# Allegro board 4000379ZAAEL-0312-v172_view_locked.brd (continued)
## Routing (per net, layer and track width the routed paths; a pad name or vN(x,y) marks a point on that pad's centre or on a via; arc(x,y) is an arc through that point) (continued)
DDR_BL3_DQ26: length 67.9
  TOP w0.102: U13.A3 95.77,15.19 95.77,12.59 95.24,12.06 89.84,12.06 82.37,19.53 82.37,37.54 82.45,37.62 85.34,37.62 85.42,37.69 85.42,37.97 85.34,38.05 83.35,38.05 83.26,38.14 83.26,38.38 83.46,38.58 85.27,38.58 85.34,38.66 85.34,39.04 85.27,39.12 84.43,39.12 84.35,39.19 84.35,39.45 84.54,39.64 85.42,39.64 85.5,39.71 85.5,40.62 85.59,40.7 86.4,40.7 86.5,40.8 86.5,41.62 94.09,49.21 96,49.21 96.47,48.74 97.06,48.74 97.19,48.87 98.68,48.87 98.79,48.76 99.04,48.76 99.37,49.08 U1.N26
DDR_BL3_DQ27: length 67.7
  TOP w0.102: U1.K27 99.24,47.68 98.81,47.68 98.68,47.55 97.87,47.55 97.19,46.86 94.93,46.86 88.77,40.71 88.77,32.64 88.7,32.56 87.76,32.56 87.68,32.64 87.68,32.97 87.76,33.05 88.21,33.05 88.29,33.12 88.29,33.38 88.21,33.45 87.86,33.45 87.78,33.53 87.78,33.78 87.86,33.86 88.21,33.86 88.29,33.93 88.29,34.32 88.21,34.39 87.35,34.39 87.27,34.32 87.27,32.64 87.2,32.56 86.94,32.56 86.87,32.64 86.87,34.32 86.79,34.39 86.54,34.39 86.46,34.32 86.46,32.64 86.39,32.56 86.13,32.56 86.06,32.64 86.06,34.32 85.98,34.39 85.72,34.39 85.65,34.32 85.65,32.64 85.57,32.56 85.32,32.56 85.24,32.64 85.24,34.32 85.17,34.39 84.89,34.39 84.81,34.32 84.81,23.97 85.58,23.2 85.58,22.8 85.7,22.68 86.09,22.68 86.23,22.54 86.23,22.28 86.33,22.17 86.6,22.17 87.05,21.73 87.05,21.51 87.14,21.41 87.41,21.41 87.53,21.3 87.53,20.91 87.66,20.78 87.91,20.78 88.04,20.65 88.04,16.97 90.49,14.51 92.97,14.51 93.12,14.66 93.12,15.47 92.99,15.6 92.16,15.6 91.77,15.99 U13.B8
DDR_BL3_DQ28: length 67.9
  TOP w0.102: U1.P27 98.91,49.51 98.68,49.28 97.05,49.28 96.93,49.15 96.7,49.15 96.14,49.71 93.69,49.71 81.76,37.78 81.76,19.24 89.55,11.46 95.49,11.46 98.57,14.53 98.57,16.42 97.79,17.2 96.42,17.2 96.01,16.79 95.77,16.79 U13.C3
DDR_BL3_DQ29: length 68
  TOP w0.102: U1.J26 99.37,47.36 99.04,47.03 98.79,47.03 98.67,47.14 98.04,47.14 97.3,46.41 95.33,46.41 90.98,42.05 90.98,35.15 90.91,35.08 90.53,35.08 90.45,35 90.45,34.77 90.53,34.7 90.91,34.7 90.98,34.62 90.98,34.32 90.91,34.24 89.53,34.24 89.46,34.16 89.46,33.78 89.53,33.71 90.91,33.71 90.98,33.63 90.98,33.32 90.91,33.25 90.45,33.25 90.37,33.17 90.37,32.61 90.45,32.54 90.91,32.54 90.98,32.46 90.98,31.95 90.91,31.88 89.99,31.88 89.92,31.95 89.92,33.17 89.84,33.25 89.53,33.25 89.46,33.17 89.46,31.95 89.38,31.88 87.15,31.88 87.07,31.8 87.07,28.75 87,28.68 86.74,28.68 86.66,28.75 86.66,31.8 86.59,31.88 86.33,31.88 86.26,31.8 86.26,28.68 86.18,28.6 85.93,28.6 85.85,28.68 85.85,31.8 85.78,31.88 85.5,31.88 85.42,31.8 85.42,24.22 88.85,20.79 88.85,17.03 89.49,16.39 92.05,16.39 92.18,16.52 92.18,17.46 92.3,17.59 92.56,17.59 U13.D7
DDR_BL3_DQ30: length 66.7
  TOP w0.102: U13.A2 96.57,15.19 96.57,15.18 96.57,15.12 96.46,15.01 96.23,15.01 96.14,15.09 96.14,15.36 95.94,15.57 95.4,15.57 95.33,15.49 95.33,12.75 94.95,12.37 89.98,12.37 82.68,19.67 82.68,37.13 82.75,37.21 86.79,37.21 86.87,37.29 86.87,37.64 86.79,37.72 85.86,37.72 85.79,37.8 85.79,38.15 85.86,38.23 86.79,38.23 86.87,38.3 86.87,38.66 86.79,38.73 85.88,38.73 85.8,38.81 85.8,39.17 85.88,39.24 86.79,39.24 86.87,39.32 86.87,39.67 86.79,39.75 86.11,39.75 86.03,39.83 86.03,40.18 86.11,40.26 86.79,40.26 86.87,40.34 86.87,41.54 94.29,48.96 95.93,48.96 96.35,48.54 97.13,48.54 97.25,48.66 98.51,48.66 U1.M29
DDR_BL3_DQ31: length 67.2
  TOP w0.102: U13.C8 91.77,16.79 91.77,17.1 91.67,17.2 90.73,17.2 90.53,17.4 90.15,17.4 90.07,17.48 90.07,17.91 89.99,17.98 89.71,17.98 89.64,17.91 89.64,17.63 89.54,17.53 89.25,17.53 89.15,17.62 89.15,20.92 85.72,24.34 85.72,28.14 85.8,28.22 87.33,28.22 87.4,28.3 87.4,31.5 87.48,31.57 91.26,31.57 91.36,31.67 91.36,32.36 91.44,32.44 92.25,32.44 92.33,32.51 92.33,32.77 92.25,32.84 91.44,32.84 91.36,32.92 91.36,33.17 91.44,33.25 92.35,33.25 92.43,33.32 92.43,33.55 92.35,33.63 91.44,33.63 91.36,33.71 91.36,33.99 91.44,34.06 92.35,34.06 92.43,34.14 92.43,34.39 92.35,34.47 91.44,34.47 91.36,34.54 91.36,34.8 91.44,34.87 92.35,34.87 92.43,34.95 92.43,35.2 92.35,35.28 91.44,35.28 91.36,35.36 91.36,35.61 91.44,35.69 92.35,35.69 92.43,35.76 92.43,36.02 92.35,36.09 91.44,36.09 91.36,36.17 91.36,36.42 91.44,36.5 92.35,36.5 92.43,36.58 92.43,36.83 92.35,36.91 91.44,36.91 91.36,36.98 91.36,37.24 91.44,37.31 92.35,37.31 92.43,37.39 92.43,37.64 92.35,37.72 91.44,37.72 91.36,37.8 91.36,38.05 91.44,38.13 92.35,38.13 92.43,38.2 92.43,38.46 92.35,38.53 91.44,38.53 91.36,38.61 91.36,38.86 91.44,38.94 92.35,38.94 92.43,39.01 92.43,39.27 92.35,39.34 91.44,39.34 91.36,39.42 91.36,39.67 91.44,39.75 92.35,39.75 92.43,39.83 92.43,40.08 92.35,40.16 91.44,40.16 91.36,40.23 91.36,40.49 91.44,40.56 92.35,40.56 92.43,40.64 92.43,40.89 92.35,40.97 91.44,40.97 91.36,41.05 91.36,41.3 91.44,41.38 92.35,41.38 92.43,41.45 92.43,41.78 92.35,41.86 91.77,41.86 91.69,41.94 91.69,42.33 95.56,46.2 97.39,46.2 98.11,46.92 U1.H29
DDR_BL3_UDM: length 67.9
  TOP w0.102: U1.M27 99.24,48.54 98.8,48.54 98.7,48.43 97.3,48.43 97.21,48.34 96.24,48.34 95.87,48.7 94.48,48.7 87.17,41.39 87.17,36.18 87.1,36.11 86.74,36.11 86.66,36.18 86.66,36.75 86.59,36.83 86.23,36.83 86.16,36.75 86.16,36.14 86.08,36.07 85.72,36.07 85.65,36.14 85.65,36.75 85.57,36.83 85.22,36.83 85.14,36.75 85.14,36.14 85.06,36.07 84.71,36.07 84.63,36.14 84.63,36.75 84.56,36.83 84.2,36.83 84.12,36.75 84.12,36.14 84.05,36.07 83.69,36.07 83.62,36.14 83.62,36.73 83.54,36.8 83.06,36.8 82.98,36.73 82.98,19.82 90.13,12.67 94.83,12.67 94.95,12.79 94.95,13.16 94.84,13.26 94.7,13.26 94.59,13.37 94.59,13.65 94.7,13.76 94.86,13.76 94.95,13.84 94.95,16.18 94.69,16.43 94.69,17.48 94.84,17.63 95.73,17.63 95.76,17.59 U13.D3
DDR_BL3_UDQS_N: length 68
  TOP w0.091: U13.B7 92.56,16.04 92.71,16.19 93.66,16.19 93.85,16 93.85,15.7 93.73,15.57 93.73,15.35 93.85,15.23 93.85,15.01 93.73,14.88 93.73,14.66 93.85,14.54 93.85,14.22 93.29,13.67 92.48,13.67 92.36,13.78 92.15,13.78 92.03,13.67 91.81,13.67 91.7,13.78 91.48,13.78 91.37,13.67 91.15,13.67 91.03,13.78 90.82,13.78 90.7,13.67 90.35,13.67 90.03,13.99 90.03,14.08 90.03,14.18 89.87,14.33 89.68,14.33 89.53,14.49 89.53,14.58 89.53,14.58 89.53,14.68 89.37,14.83 89.18,14.83 89.03,14.99 89.03,15.08 89.03,15.17 88.87,15.33 88.68,15.33 88.53,15.48 88.53,15.58 88.53,15.58 88.53,15.67 88.38,15.83 88.18,15.83 88.03,15.98 88.03,16.08 88.03,16.17 87.88,16.33 87.69,16.33 87.53,16.48 87.53,19.67 87.24,19.97 86.65,19.97 86.36,19.67 86.36,18.56 86.27,18.47 85.97,18.47 85.88,18.56 85.88,21.72 85.59,22.01 84.91,22.01 84.62,21.72 84.62,19.9 84.53,19.81 84.14,19.81 83.95,20 83.95,22.88 84.26,23.19 84.26,24.04 83.95,24.36 83.95,25.2 84.26,25.52 84.26,26.37 83.95,26.68 83.95,27.52 84.26,27.84 84.26,28.69 83.95,29 83.95,29.84 84.26,30.16 84.26,31.01 83.88,31.39 83.88,32.1 84.26,32.48 84.26,33.33 83.88,33.71 83.88,34.8 84.15,35.07 87.56,35.07 88.01,35.52 88.01,36.74 88.2,36.93 88.2,38.03 88.01,38.23 88.01,39.01 88.23,39.23 88.23,40.28 88.01,40.5 88.01,40.96 88.61,41.56 89.06,41.56 89.66,42.16 89.66,42.6 90.15,43.1 90.6,43.1 91.2,43.7 91.2,44.08 91.75,44.64 92.13,44.64 92.74,45.24 92.74,45.75 93.17,46.18 93.67,46.18 94.28,46.78 94.28,47.22 94.98,47.92 95.63,47.92 95.83,47.72 97.44,47.72 97.71,47.99 98.71,47.99 98.79,47.9 99.05,47.9 99.36,48.22 U1.L26
DDR_BL3_UDQS_P: length 68.2
  TOP w0.091: U1.L28 98.92,48.22 98.92,48.23 97.46,48.23 97.3,48.07 95.97,48.07 95.77,48.27 94.83,48.27 93.93,47.37 93.93,46.92 93.53,46.52 93.02,46.52 92.39,45.89 92.39,45.38 91.99,44.98 91.61,44.98 90.85,44.22 90.85,43.84 90.45,43.44 90.01,43.44 89.31,42.75 89.31,42.3 88.91,41.9 88.47,41.9 87.67,41.1 87.67,40.35 87.88,40.13 87.88,39.37 87.67,39.15 87.67,38.08 87.86,37.89 87.86,37.07 87.67,36.88 87.67,35.66 87.42,35.41 84.01,35.41 83.54,34.94 83.54,33.57 83.92,33.19 83.92,32.62 83.54,32.24 83.54,31.25 83.92,30.87 83.92,30.3 83.6,29.98 83.6,28.86 83.92,28.54 83.92,27.98 83.6,27.66 83.6,26.54 83.92,26.22 83.92,25.66 83.6,25.34 83.6,24.22 83.92,23.9 83.92,23.34 83.6,23.02 83.6,19.86 83.99,19.47 84.67,19.47 84.96,19.76 84.96,21.58 85.05,21.67 85.44,21.67 85.53,21.58 85.53,18.41 85.83,18.12 86.41,18.12 86.71,18.41 86.71,19.53 86.8,19.62 87.09,19.62 87.19,19.53 87.19,16.34 90.2,13.32 93.44,13.32 94.2,14.08 94.2,16.15 93.81,16.54 92.81,16.54 U13.C7
DDR_CAS_N: length 91.2
  TOP w0.102: v1(115.58,22.02) 115.76,22.02 U12.K3 ; v1(95.15,22.05) 95.42,22.05 U13.K3 ; v1(106.08,41) 106.35,41.27 106.35,43.03 105.65,43.74 105.65,44.09 U1.A13
  BOTTOM w0.102: v1(106.08,41) 106.08,40.73 105.99,40.64 104.69,40.64 104.3,40.26 104.3,39.99 104.24,39.93 103.73,39.93 103.63,40.03 103.63,40.39 103.56,40.46 103.3,40.46 103.23,40.39 103.23,40.01 103.15,39.93 94.43,39.93 94.36,40.01 94.36,40.21 94.28,40.28 94.11,40.28 94.03,40.21 94.03,40.01 93.95,39.93 87.52,39.93 84.12,36.53 84.12,24.61 84.48,24.26 84.66,24.26 84.73,24.33 84.73,24.78 84.8,24.84 85.06,24.84 85.14,24.77 85.14,23.95 85.22,23.88 85.47,23.88 85.55,23.95 85.55,24.78 85.61,24.84 88.7,24.84 89.03,24.51 90,24.51 90.72,23.79 92.01,23.79 92.25,24.03 93.14,24.03 93.78,23.39 93.78,23.19 94.92,22.05 v1(95.15,22.05) 95.43,21.77 105.08,21.77 105.16,21.84 105.16,22 105.08,22.07 104.88,22.07 104.8,22.15 104.8,22.3 104.88,22.38 105.08,22.38 105.16,22.45 105.16,22.66 105.08,22.73 104.88,22.73 104.8,22.81 104.8,22.96 104.88,23.04 105.08,23.04 105.16,23.11 105.16,23.27 105.08,23.34 104.88,23.34 104.8,23.42 104.8,23.65 104.88,23.72 108.12,23.72 108.73,24.33 109.74,24.33 110.29,23.79 112.42,23.79 112.66,24.03 113.57,24.03 114.5,23.09 114.5,22.81 115.29,22.02 115.58,22.02 v1(115.58,22.02) 115.61,22.02 115.92,21.7 120.01,21.7 120.91,20.8 121.55,20.8 123.16,20.8 R127.2
DDR_CK_N: length 82.4
  TOP w0.091: v1(93.47,20.92) 93.46,20.92 93.35,21.03 93.34,21.05 93.34,21.87 93.02,22.2 92.75,22.2 U13.K7 ; v3(105.85,42.6) 105.66,42.79 105.66,43.39 105.4,43.65 105.4,44.31 U1.B14 ; v1(113.78,21) 113.71,21.07 113.71,21.72 113.34,22.09 113.07,22.09 112.93,22.22 U12.K7
  BOTTOM w0.091: R133.1 113.9,21 v1(113.78,21) 113.64,20.86 113.52,20.86 113.46,20.92 110.48,20.92 107.52,17.96 96.54,17.96 93.68,20.83 93.58,20.83 93.5,20.92 v1(93.47,20.92) 93.01,20.93 92.69,20.93 92.28,21.34 91.62,21.34 91.51,21.45 91.29,21.45 91.17,21.34 90.96,21.34 90.84,21.45 90.62,21.45 90.51,21.34 90.29,21.34 90.18,21.45 89.96,21.45 89.84,21.34 89.62,21.34 89.51,21.45 89.29,21.45 89.18,21.34 88.96,21.34 88.84,21.45 88.63,21.45 88.51,21.34 88.29,21.34 88.18,21.45 87.96,21.45 87.85,21.34 87.63,21.34 87.51,21.45 87.3,21.45 87.18,21.34 84.68,21.34 82.14,23.88 82.14,37.24 86.65,41.74 105.3,41.74 105.68,42.12 105.68,42.43 105.85,42.6 v3(105.85,42.6)
DDR_CK_P: length 82.3
  TOP w0.091: U12.J7 112.93,21.64 113.03,21.74 113.19,21.74 113.36,21.57 113.36,20.51 v1(113.47,20.37) ; U1.C15 104.9,44.81 104.9,44.32 105.05,44.17 105.05,43.51 105.32,43.25 105.32,42.94 105.32,42.93 105.32,42.68 105.21,42.57 v3(105.21,42.57) ; v1(93.1,20.37) 93,20.47 93,21.73 92.87,21.86 92.7,21.86 92.56,21.72 U13.J7
  BOTTOM w0.091: R133.2 114.02,20.19 113.84,20.37 v1(113.47,20.37) 113.3,20.54 110.63,20.54 107.71,17.61 96.4,17.61 93.57,20.45 93.17,20.45 v1(93.1,20.37) 92.89,20.58 92.55,20.58 92.14,20.99 84.54,20.99 81.8,23.73 81.8,37.38 86.51,42.09 105.16,42.09 105.33,42.27 105.33,42.45 v3(105.21,42.57)
DDR_CKE_0: length 94.6
  TOP w0.102: v1(110.94,22.79) 111.33,22.39 ; 111.33,22.39 111.34,22.39 ; 111.33,22.39 U12.K9 ; U1.B7 107.81,44.49 107.98,44.32 107.98,42.48 v1(108.27,42.19) ; U13.K9 90.97,22.39 v1(91.37,22.79)
  BOTTOM w0.102: v1(108.27,42.19) 107.91,42.55 107.12,42.55 106.38,41.8 106.38,41.57 106.24,41.43 105.79,41.43 105.31,40.94 104.55,40.94 104.34,41.15 87.45,41.15 83.21,36.91 83.21,24.31 85.01,22.5 87.2,22.5 87.27,22.58 87.27,23.8 87.38,23.9 88.09,23.9 88.19,23.8 88.19,23.01 88.29,22.91 88.49,22.91 88.6,23.01 88.6,23.76 88.73,23.9 89.74,23.9 90.86,22.79 v1(91.37,22.79) 91.37,22.9 91.64,23.18 92.39,23.18 92.63,22.94 92.63,22.68 92.79,22.53 93.47,22.53 94.84,21.16 106.4,21.16 106.64,21.4 106.64,22.71 106.72,22.78 106.96,22.78 107.04,22.71 107.04,22.32 107.11,22.24 107.33,22.24 107.44,22.35 107.44,22.98 107.54,23.08 107.8,23.08 107.87,23 107.87,22.35 107.95,22.28 108.15,22.28 108.22,22.35 108.22,22.95 108.55,23.28 108.71,23.28 108.81,23.38 108.81,23.55 108.98,23.71 109.42,23.71 109.71,23.43 109.71,23.27 109.8,23.17 110.56,23.17 v1(110.94,22.79) 111.33,23.18 112.85,23.18 113.03,23 113.03,22.67 113.15,22.56 113.89,22.56 115.35,21.09 119.54,21.09 121.35,19.28 121.35,19.16 R126.2
DDR_CS_0: length 85.6
  TOP w0.102: v1(108.51,40.92) 107.9,40.92 107.57,41.25 107.57,43.5 107.09,43.99 107.09,44.35 106.94,44.49 U1.B10 ; v1(118.35,23.36) 118.11,23.6 117.35,23.6 116.94,23.19 U12.L2 ; v1(97.82,23.52) 97.76,23.57 96.95,23.57 96.57,23.19 U13.L2
  BOTTOM w0.102: R130.2 121.39,23.36 121.23,23.52 121.23,23.54 118.82,23.54 118.64,23.37 118.36,23.37 v1(118.35,23.36) 118.16,23.55 117.11,23.55 116.88,23.32 116.15,23.32 115.74,23.72 115.31,23.72 114.63,24.4 114.63,24.69 113.86,25.46 112.66,25.46 112,24.8 111.47,24.8 111.23,25.04 111.23,25.46 111.12,25.57 110.45,25.57 109.9,26.12 109.29,26.12 109.24,26.06 109.02,26.06 107.77,24.82 102.87,24.82 101.12,23.06 98.43,23.06 97.96,23.52 97.82,23.52 v1(97.82,23.52) 97.8,23.53 96.85,23.53 96.7,23.38 95.73,23.38 95.36,23.75 94.93,23.75 94.31,24.37 94.31,24.65 93.49,25.48 92.26,25.48 91.59,24.8 91.14,24.8 88.41,27.53 87.25,27.53 87.17,27.46 87.17,27.23 87.1,27.15 86.26,27.15 86.18,27.08 86.18,26.7 86.13,26.64 85.72,26.64 85.65,26.72 85.65,35.9 88.16,38.41 103.78,38.41 104.06,38.13 106.59,38.13 107.44,38.98 107.44,39.64 108.51,40.7 v1(108.51,40.92)
DDR_ODT_0: length 85.5
  TOP w0.102: U12.K1 118.15,22.39 v1(118.29,22.53) ; U1.A9 107.37,44.09 107.78,43.68 107.78,41.8 v1(108.08,41.5) ; U13.K1 97.37,22.39 97.66,22.68 v1(97.78,22.68)
  BOTTOM w0.102: v1(108.08,41.5) 108.08,40.96 105.85,38.73 104.31,38.73 104.03,39.02 87.9,39.02 85.04,36.15 85.04,25.93 85.27,25.7 87.4,25.7 87.63,25.93 87.63,26.63 87.92,26.92 88.45,26.92 90.97,24.4 91.75,24.4 92.43,25.07 93.29,25.07 93.73,24.64 93.73,24.37 94.76,23.34 95.15,23.34 95.68,22.81 95.68,22.71 96.01,22.38 97.36,22.38 97.66,22.68 v1(97.78,22.68) 97.99,22.68 98.12,22.55 102.21,22.55 102.44,22.78 103.58,22.78 103.73,22.94 103.73,23.11 103.66,23.19 103.4,23.19 103.33,23.27 103.33,23.52 103.4,23.6 103.66,23.6 103.73,23.67 103.73,23.93 103.66,24 103.4,24 103.33,24.08 103.33,24.31 103.4,24.38 107.91,24.38 108.52,24.99 109.95,24.99 110.54,24.4 112.17,24.4 112.83,25.06 113.69,25.06 114.15,24.6 114.15,24.31 115.14,23.32 115.47,23.32 116.43,22.35 118.11,22.35 v1(118.29,22.53) 118.47,22.35 121.34,22.35 R128.2
DDR_PAR: length 1.3
  TOP w0.127: U1.F14 105.28,46.18 v1(105.64,45.82)
  BOTTOM w0.102: v1(105.64,45.82) 105.64,45.13 R131.2
DDR_RAS_N: length 89.5
  TOP w0.102: v1(106.58,38.79) 106.56,38.81 106.56,43.12 105.87,43.8 105.87,44.26 105.65,44.49 105.65,44.92 U1.C13 ; U12.J3 116.14,21.59 116.54,21.99 v1(116.54,22.82) ; U13.J3 95.77,21.59 96.19,22.02 96.19,22.77 v1(96.18,22.79)
  BOTTOM w0.102: R122.2 121.15,22.81 120.67,23.28 119.09,23.28 118.75,22.94 117.97,22.94 117.68,23.23 117.2,23.23 116.78,22.82 116.55,22.82 v1(116.54,22.82) 116.54,22.82 116.27,22.82 115.57,23.52 115.23,23.52 114.37,24.38 114.37,24.67 113.78,25.26 112.74,25.26 112.08,24.6 110.63,24.6 110.03,25.2 108.44,25.2 107.86,24.61 103.15,24.61 103.07,24.54 103.07,23.34 102.79,23.06 102.26,23.06 102.01,22.81 98.33,22.81 98.04,23.1 97.32,23.1 97.17,23.25 96.86,23.25 96.77,23.16 96.54,23.16 96.43,23.05 96.43,22.91 96.33,22.81 96.19,22.81 v1(96.18,22.79) 96.01,22.79 95.25,23.55 94.84,23.55 94.09,24.29 94.09,24.58 93.4,25.27 92.34,25.27 91.67,24.6 91.06,24.6 88.43,27.23 87.48,27.23 87.4,27.15 87.4,26.09 87.33,26.01 87.05,26.01 86.97,26.09 86.97,26.77 86.89,26.85 86.66,26.85 86.56,26.75 86.56,26.14 86.44,26.01 85.42,26.01 85.34,26.09 85.34,36.03 88.03,38.71 103.9,38.71 104.21,38.41 106.2,38.41 v1(106.58,38.79)
DDR_RST: length 80.9
  TOP w0.102: U13.T2 96.57,27.19 96.6,27.19 96.6,29.07 v1(96.61,29.07) ; v1(102.11,32.13) 102.21,32.23 102.21,33.07 102.13,33.15 100.97,33.15 100.89,33.07 100.89,32.82 100.97,32.74 101.22,32.74 101.3,32.66 101.3,32.11 101.22,32.03 100.86,32.03 100.79,32.11 100.79,32.26 100.71,32.33 100.36,32.33 100.28,32.26 100.28,32.11 100.2,32.03 99.9,32.03 99.82,32.11 99.82,32.69 99.87,32.74 100.41,32.74 100.48,32.82 100.48,33.07 100.41,33.15 99.9,33.15 99.82,33.22 99.82,33.48 99.9,33.55 102.13,33.55 102.21,33.63 102.21,33.88 102.13,33.96 99.9,33.96 99.82,34.04 99.82,34.29 99.9,34.37 102.13,34.37 102.21,34.44 102.21,34.7 102.13,34.77 99.9,34.77 99.82,34.85 99.82,35.1 99.9,35.18 100.43,35.18 100.51,35.26 100.51,35.51 100.43,35.59 99.9,35.59 99.82,35.66 99.82,35.92 99.9,35.99 100.43,35.99 100.51,36.07 100.51,36.32 100.43,36.4 99.9,36.4 99.82,36.47 99.82,36.73 99.9,36.8 100.43,36.8 100.51,36.88 100.51,37.13 100.43,37.21 99.9,37.21 99.82,37.29 99.82,37.54 99.9,37.62 100.43,37.62 100.51,37.69 100.51,37.95 100.43,38.02 99.9,38.02 99.82,38.1 99.82,38.35 99.9,38.43 100.43,38.43 100.51,38.51 100.51,38.76 100.43,38.84 99.9,38.84 99.82,38.91 99.82,39.17 99.9,39.24 100.43,39.24 100.51,39.32 100.51,39.57 100.43,39.65 99.9,39.65 99.82,39.73 99.82,39.98 99.9,40.06 100.43,40.06 100.51,40.13 100.51,40.39 100.43,40.46 99.9,40.46 99.82,40.54 99.82,40.79 99.9,40.87 100.43,40.87 100.51,40.94 100.51,41.2 100.43,41.27 99.9,41.27 99.82,41.35 99.82,41.61 99.9,41.68 100.43,41.68 100.51,41.76 100.51,42.55 100.87,42.91 100.87,43.64 100.77,43.74 100.77,44.37 100.9,44.49 U1.B24 ; v1(116.84,29.16) 116.99,29 116.99,27.25 116.94,27.19 U12.T2
  BOTTOM w0.102: v1(116.84,29.16) 115.46,30.53 104.22,30.53 104.14,30.45 104.14,30.07 104.06,30 103.66,30 103.58,30.07 103.58,30.48 103.53,30.53 103.2,30.53 103.12,30.45 103.12,30.12 103.05,30.05 102.64,30.05 102.57,30.12 102.57,30.45 102.49,30.53 98.88,30.53 97.36,29.01 96.67,29.01 v1(96.61,29.07) 96.57,29.07 96.47,29.17 96.47,29.51 96.55,29.59 97.36,29.59 97.43,29.67 97.43,29.92 97.36,30 96.55,30 96.47,30.07 96.47,30.33 96.55,30.4 97.87,30.4 97.94,30.48 97.94,30.73 97.87,30.81 96.55,30.81 96.47,30.89 96.47,31.22 96.55,31.29 98.27,31.29 98.35,31.22 98.35,31.04 98.45,30.94 98.68,30.94 98.76,31.01 98.76,31.19 98.83,31.27 99.09,31.27 99.16,31.19 99.16,31.01 99.24,30.94 99.49,30.94 99.57,31.01 99.57,31.17 99.64,31.24 99.9,31.24 99.97,31.17 99.97,31.01 100.05,30.94 100.41,30.94 100.48,31.01 100.48,31.17 100.56,31.24 100.91,31.24 100.99,31.17 100.99,30.99 101.07,30.91 101.42,30.91 102.11,31.6 ; 102.11,31.6 v1(102.11,32.13) ; 102.11,31.6 C24.1
DDR_WE_N: length 91.8
  TOP w0.102: U1.D16 104.35,45.33 104.35,44.92 104.67,44.6 104.67,44.37 104.56,44.25 104.56,42.22 105.1,41.68 105.46,41.68 105.62,41.52 105.62,40.55 105.7,40.46 106.12,40.46 106.22,40.36 106.22,40.13 106.15,40.06 105.69,40.06 105.61,39.98 105.61,39.83 105.69,39.75 106.15,39.75 106.22,39.67 106.22,39.4 106.11,39.29 105.75,39.29 v1(105.7,39.26) ; v1(115.33,22.86) 115.8,22.86 U12.L3 ; 95.76,23.19 95.42,23.19 95.42,23.18 95.17,22.94 v1(94.95,22.94) ; 95.76,23.19 95.77,23.19 ; 95.76,23.19 U13.L3
  BOTTOM w0.102: R951.2 121.1,21.78 120.75,22.12 116.37,22.12 115.63,22.86 v1(115.33,22.86) 115.31,22.86 113.93,24.25 113.93,24.53 113.61,24.85 112.91,24.85 112.25,24.19 110.46,24.19 109.86,24.79 108.61,24.79 108,24.18 104.11,24.18 104.04,24.1 104.04,22.3 103.96,22.23 103.76,22.23 103.68,22.3 103.68,22.45 103.61,22.53 103.4,22.53 103.33,22.45 103.33,22.28 103.25,22.2 103.05,22.2 102.97,22.28 102.97,22.45 102.9,22.53 102.64,22.53 102.57,22.45 102.57,22.25 102.49,22.17 102.29,22.17 102.18,22.28 102.01,22.28 101.9,22.17 95.91,22.17 95.15,22.94 v1(94.95,22.94) 94.84,22.94 93.5,24.28 93.5,24.56 93.22,24.84 92.49,24.84 91.84,24.19 90.89,24.19 89.4,25.68 89.18,25.68 88.87,25.98 88.87,26.21 88.44,26.64 87.97,26.64 87.88,26.56 87.88,25.93 88.14,25.67 88.14,25.53 88.01,25.4 84.81,25.4 84.73,25.48 84.73,36.28 87.78,39.32 104.16,39.32 104.4,39.08 105.52,39.08 v1(105.7,39.26)
DDR_ZQ_0: length 5.4
  TOP w0.102: U12.L8 112.14,23.19 111.75,23.57 110.91,23.57 110.53,23.2 110.53,22.38 110.4,22.25 108.2,22.25 108.05,22.4 R135.1
DDR_ZQ_1: length 7.1
  TOP w0.102: U13.L8 91.77,23.19 91.38,23.57 90.75,23.57 90.6,23.42 90.6,22.65 90.37,22.42 89.94,22.42 89.05,23.3 89.05,24.61 88.41,25.25 87.78,25.25 R136.1
DUT_AVDDHC_3V3: length 165.8
  TOP w0.305: EC21.1 119.63,100.2 ; EC16.1 104.61,91.31
  TOP w0.508: 104.61,92.03 104.61,89.7 v1(104.65,89.66) 104.85,89.46 SR71.2 SR76.2 104.85,86.34 v1(104.6,86.08) 104.6,84.01 105.11,83.5 v1(105.66,83.5) ; 104.61,92.03 104.61,93.6 105.11,94.11 v1(105.98,94.11) ; 104.61,92.03 v1(105.83,92.03) ; SC264.1 SR88.1 SR90.1 ; SC264.1 126.57,77.52 v2(126.36,77.72) ; SC264.1 127.64,77.52 127.89,77.77 SD2.C 129.89,77.77 130.48,77.18 U108.VCC ; v2(106.93,99) 107.7,99.77 EC17.1 108.15,100.2 120.9,100.2 121.28,99.82 ; v2(120.55,78.97) 116.47,78.97 v2(116.05,78.55) 113.16,78.55 v4(111.82,79.88) ; 118.96,87.14 119.04,87.06 SR73.1 ; 114.89,86.76 v1(114.89,86.13) 114.89,85.35 SC138.1 ; v1(117.43,86.27) 117.43,87.16 ; SR157.1 v2(138.94,93.15) ; v2(139.89,94.04) 139.88,94.06 SC269.1 J1.1 ; SR153.1 v2(138.94,88.96) ; v2(129.16,90.47) 129.13,90.5 EC19.1 ; SR64.2 106.11,79.04 106.62,79.55 106.62,80.46 106.26,80.82 SR65.2 105.39,80.82 105.22,80.64 U5.8 104.02,80.9 103.06,80.9 102.55,80.39 v2(102.55,79.5) 102.55,76.52 103.06,76.01 105.52,76.01 SR67.2 106,76.33 SR57.1
  L2 w0.508: v1(123.85,86.08) 123.85,87.42 124.38,87.96 124.38,88.58 ; 124.38,88.58 126.28,90.47 v2(129.16,90.47) ; 124.38,88.58 124.33,88.58 123.62,89.28 121.79,89.28 121.47,89.6 v1(121.47,89.64)
  L3 w0.508: v2(138.94,88.96) v2(138.94,93.15) 139,93.15 v2(139.89,94.04)
  BOTTOM w0.127: SR41.2 105.83,92.88 105.83,92.86
  BOTTOM w0.203: v1(121.36,88.97) 121.72,88.61 U66.97 ; v1(117.43,86.27) 117.43,86.25 117.7,85.99 U66.127 ; U66.17 113.57,89.61 113.94,89.24 v1(113.94,88.95) ; 121.57,89.75 121.94,90.11 U66.91 ; v1(114.89,86.13) 114.7,85.93 U66.139 ; v1(123.85,86.08) 123.57,86.36 U66.106 ; U66.7 113.53,87.11 v1(113.94,87.52)
  BOTTOM w0.254: U66.61 119.2,94.25 v1(119.46,93.99) ; U66.49 116.2,94.27 115.92,94 v1(115.78,94) ; v1(120.57,94) 120.94,94 121.2,94.25 U66.69 ; U66.41 114.2,94.32 114.58,93.94 v1(114.7,93.94) ; 121.57,89.75 v1(121.47,89.64)
  BOTTOM w0.305: EC20.1 131.19,94.87
  BOTTOM w0.508: SR96.2 105.83,91.29 v1(105.83,92.03) 105.83,92.86 ; v2(139.89,94.04) 139.06,94.87 SR56.2 SC242.1 SR51.2 SR127.2 129.72,91.03 v2(129.16,90.47) ; 106.11,79.5 108.96,79.5 ; 106.11,79.5 SR613.1 ; 106.11,79.5 104.2,79.5 ; 108.96,79.5 108.96,81.23 SR612.1 ; 108.96,79.5 111.44,79.5 v4(111.82,79.88) SR611.1 ; SR62.1 115.7,78.19 v2(116.05,78.55) ; SC509.1 122.81,78.67 ; 122.81,78.67 124.57,78.67 RP1131.2 125.03,79.06 v2(126.36,77.72) ; 122.81,78.67 122.75,78.72 SC130.1 120.79,78.72 v2(120.55,78.97) ; SR85.1 104.37,86.28 104.57,86.08 v1(104.6,86.08) ; U7.8 98.85,86.9 SC157.1 ; SC157.1 96.99,85.94 TP25.1 96.96,85.18 97.82,84.33 98.94,84.33 SR81.1 ; SC157.1 96.61,86.9 95.65,87.86 95.65,90.28 96.05,90.68 SR84.1 SR98.1 SR80.1 ; v1(123.85,86.08) 124.08,85.85 EC22.1 ; 101.03,82.61 101.03,80.01 101.54,79.5 v2(102.55,79.5) 104.2,79.5 ; v2(106.93,99) 105.87,97.95 SR58.2 SR49.2 105.87,94.22 v1(105.98,94.11) ; SR39.2 SR43.2 104.85,89.46 v1(104.65,89.66) ; 104.2,79.5 SR614.1
  vias: v1(106.3,83.5) v1(106.87,83.5)
DUT_AVDDL_1GXG_0V95: length 3.2
  TOP w0.508: v3(117.65,96.03) 117.62,96.06 117.62,96.64 SC218.1 SC219.1 SL17.2
  BOTTOM w0.203: v3(117.65,96.03) 117.65,96.03 117.45,95.83 U66.54
DUT_AVDDLC_0V95: length 118.7
  TOP w0.127: 118.6,85.61 SC469.1
  TOP w0.508: 109.98,82.6 109.96,82.63 109.63,82.3 ; v1(118.26,86.25) 118.68,86.25 ; 118.68,86.25 v1(119.08,86.25) ; 118.68,86.25 118.6,86.17 118.6,85.61 ; v1(121.56,86.23) 122.04,86.72 SC470.1 ; SC472.1 122.38,90.43 122.74,90.07 126.94,90.07 127.3,90.43 127.3,92.43 127.25,92.48 ; SL17.1 115.84,98.11 116.41,98.68 118.95,98.68 SC466.1 119.38,98.09 119.38,97.07 v1(119.53,96.92) ; SL29.1 122.1,82.47 121.31,81.69 118.03,81.69 117.53,82.19 117.53,83.62 v1(117.81,83.9) 118.09,83.9 118.6,84.41 SC517.1 SC469.1
  TOP w0.762: 103.89,95.17 103.63,94.92 103.63,83.26 104.6,82.3 109.63,82.3
  TOP w1.016: SC467.1 125.76,94.03 126.62,94.03 127,94.41 127,99.72 124.33,102.39 107.01,102.39 105.44,100.81 105.44,100.79
  L2 w1.27: v2(133.4,92.89) v2(134.47,92.89) 134.65,92.89 136.12,91.41 136.12,85.09 134.81,83.78 v2(131.67,83.78) v2(130.28,83.78)
  BOTTOM w0.203: U66.141 114.2,85.97 v1(114.04,86.13) 114.02,86.13 113.7,85.81 U66.143 ; v1(121.64,90.55) 121.7,90.61 U66.89 ; v1(121.18,83.52) 120.95,83.76 U66.114 ; U66.99 121.58,88.11 ; 121.58,88.11 v1(121.46,88.11) ; 121.58,88.11 121.58,87.97 121.94,87.61 U66.101 ; U66.48 116.01,95.53 116.01,96.79 v1(115.85,96.96) ; v1(111.65,85.56) 111.96,85.86 U66.2 ; v1(117.81,83.9) 117.81,83.97 117.95,84.1 U66.126 ; v1(123.75,88.16) 123.75,88.07 123.55,87.86 U66.100 ; v1(121.56,91.08) 121.59,91.11 U66.87 ; v1(118.26,86.25) 118.2,86.19 U66.125 ; v1(121.69,92.78) 121.86,92.61 U66.81 ; U66.121 119.2,86.14 v1(119.08,86.25) ; v1(121.66,93.34) 121.69,93.32 121.87,93.32 122.07,93.11 U66.79 ; 121.56,86.28 121.89,86.61 U66.105 ; U66.1 v1(112.35,84.86) ; v1(119.53,96.92) 119.38,96.77 119.38,95.89 119.45,95.82 U66.62 ; U66.32 112.29,93.3 v1(110.43,93.3) ; v1(121.62,93.94) 121.7,94.01 U66.71 ; v1(124.3,93.16) 124.26,93.21 123.54,93.21 123.39,93.36 U66.78
  BOTTOM w0.254: U66.21 113.78,90.61 v1(113.89,90.73) ; U66.5 113.63,86.61 113.66,86.58 v1(113.71,86.58) 113.71,86.53 113.29,86.11 U66.3 ; U66.39 113.68,94.7 113.68,94.07 v1(113.81,93.94) ; v1(121.56,86.23) 121.56,86.28 ; U66.29 113.7,92.61 v1(113.81,92.73) ; U66.19 113.15,90.06 v1(113.94,90.06) ; U66.31 113.5,93.11 v1(113.75,93.37)
  BOTTOM w0.508: SC153.1 v1(117.81,83.9)
  vias: v1(110.11,83.76) v1(110.93,83.76)
DUT_SVDDLCMU_0V95: length 11.8
  TOP w0.508: v2(119.91,82.82) 119.91,83.66 121.03,84.78 SC136.1 121.22,84.69 122.09,84.69 SL29.2 122.11,84.69 v2(123.01,84.69)
  BOTTOM w0.203: U66.118 119.95,84.59 120.02,84.52 120.02,82.93 v2(119.91,82.82)
  BOTTOM w0.254: U66.111 122.56,85.51 123.01,85.06 v2(123.01,84.69)
  BOTTOM w0.381: v2(119.91,82.82) 119.57,82.49 SC134.1
  BOTTOM w0.508: SC141.1 124.41,83.67 SC135.1 123.1,84.61 v2(123.01,84.69)
EAR_GND: length 15.1
  TOP w1.27: C241.1 57.72,151.35 C238.1
  vias: v2(60.83,148.84) v2(60.9,147.83) v2(61.72,148.84) v2(61.72,147.83) v2(62.48,148.84) v2(62.48,147.83) v2(66.1,125.67) v2(66.1,124.84) v2(66.93,125.67) v2(66.93,124.84) v2(66.93,123.95) v2(66.93,123.13) v2(131.83,145.92) v2(131.88,144.96) v2(132.59,144.15) v2(132.97,145.92) v2(132.97,145.03) v2(133.6,144.15) v2(133.99,145.92) v2(133.99,145.03) v2(134.62,144.15) v2(135,145.92) v2(135,145.03) v2(142.3,125.54) v2(142.37,124.52) v2(143.19,125.54) v2(143.19,124.52) v2(143.95,125.54) v2(143.95,124.52)
EE_M_SCL: length 2.7
  TOP w0.127: U5.6 104.35,78.18 SR64.1 106.84,78.18 SR69.1
EE_M_SDA: length 2.8
  TOP w0.127: SR70.1 106.87,77.26 SR67.1 105.59,77.26 105.16,76.83 U5.5
EE_SCL: length 23
  TOP w0.127: v4(58.7,32.86) 58.91,33.07 U601.25
  BOTTOM w0.127: R639.2 49.61,25.45 50.09,25.45 R642.2 50.59,25.24 50.74,25.1 50.74,22.48 51.31,21.91 57.06,21.91 58.59,23.43 58.59,32.75 v4(58.7,32.86)
EE_SDA: length 23.6
  TOP w0.127: v4(58.04,32.59) 58.04,33.27 58.36,33.59 U601.24
  BOTTOM w0.127: v4(58.04,32.59) 58.04,32.59 58.33,32.3 58.33,23.53 56.96,22.16 51.44,22.16 50.99,22.61 50.99,25.43 R644.2 50.06,25.9 49.63,25.9 R633.2
ETH1_MDC: length 3.8
  BOTTOM w0.127: U66.96 124.99,88.86 125.9,87.95 SR138.2
ETH1_MDIO: length 4.2
  BOTTOM w0.127: SR136.2 126.41,87 124.81,88.6 123.42,88.6 123.19,88.36 U66.98
FXM_CLKMD: length 7.2
  TOP w0.102: R172.2 92.46,50.16 93.22,50.16 93.45,49.94 97.56,49.94 97.64,49.86 98.82,49.86 98.91,49.95 98.92,49.94 U1.R28
FXM_DDR_ZQ: length 1.3
  TOP w0.127: v1(107.23,45.77) 106.91,46.18 U1.F10
  BOTTOM w0.102: v1(107.23,45.77) 107.29,45.71 R174.1
FXM_FSOURCE: length 1.6
  TOP w0.254: U1.K25 100.4,47.8 v1(100.8,47.42)
  BOTTOM w0.127: R278.1 100.03,46.92 100.31,46.92 v1(100.8,47.42)
FXM_GPIO0: length 32.3
  TOP w0.102: U1.V27 99.27,51.16 98.81,51.16 98.65,51 98.32,51 98.3,51.03 95.45,51.03
  TOP w0.127: U18.6 75.5,45.59 75.76,45.85 75.76,48.82 R156.1 R155.2 75.77,50.37 79.44,54.04 92.44,54.04 95.45,51.03
FXM_GPIO1: length 30.1
  TOP w0.102: U1.U28 98.2,50.81 98.18,50.83 95.28,50.83
  TOP w0.127: U18.1 81.79,43.05 80.64,44.2 80.64,48.69 R182.1 R181.2 80.5,51.48 82.78,53.76 92.34,53.76 95.28,50.83
FXM_GPIO2: length 30.7
  TOP w0.102: 95.65,51.24 U1.V29
  TOP w0.127: 95.65,51.24 92.57,54.32 79.27,54.32 73.91,48.96 73.91,47.12 74.17,46.86 U18.5
FXM_GPIO3: length 29.7
  TOP w0.102: 94.92,50.8 95.1,50.62 97.99,50.62 98.01,50.6 98.69,50.6 98.79,50.49 99.02,50.49 99.76,51.23 U1.W26
  TOP w0.127: 94.92,50.8 92.25,53.47 82.99,53.47 81.09,51.56 81.09,44.7 81.47,44.32 U18.2
FXM_GPIO4: length 49.9
  TOP w0.102: 95.99,51.66 98.89,51.66 98.92,51.66 U1.W28
  TOP w0.127: U18.3 83.12,45.59 83.25,45.47 83.25,42.67 82.55,41.97 75.95,41.97 75.69,42.23 75.69,43.12 75.12,43.69 73.79,43.69 73.28,44.2 73.28,49.34 78.79,54.85 92.8,54.85 95.99,51.66
FXM_GPIO5: length 35.4
  TOP w0.102: U1.Y27 99.36,52.1 99.36,51.66 99.05,51.36 98.79,51.36 98.69,51.46 95.81,51.46
  TOP w0.127: 95.81,51.46 92.7,54.57 79.02,54.57 73.6,49.15 73.6,44.7 73.98,44.32 U18.7
FXM_JRST_N: length 14.6
  TOP w0.102: U1.U2 111.82,50.81 111.92,50.91 116.42,50.91 118.19,52.68 122.1,52.68 122.38,52.96 R274.2 R83.1
FXM_JTCK: length 16.9
  TOP w0.102: v1(108.08,45.85) 107.74,46.19 U1.F8
  TOP w0.127: v4(122.81,45.15) 122.43,45.53 R94.1
  BOTTOM w0.102: v4(122.81,45.15) 122.65,44.99 108.93,44.99 v1(108.08,45.85)
FXM_JTDI: length 13.4
  TOP w0.102: R89.1 120.98,52.91 118.06,52.91 116.29,51.14 111.87,51.14 111.73,51 110.24,51 110.13,51.1 109.87,51.1 109.57,50.81 U1.U4
FXM_JTDO: length 13.9
  TOP w0.102: v1(108.15,51.51) 108.53,51.14 U1.U6 ; v1(116.59,52.4) 117.17,52.4 118.11,53.34 R192.1 R191.2
  BOTTOM w0.102: v1(108.15,51.51) 108.31,51.66 110.31,51.66 111,52.35 114.25,52.35 114.68,52.78 116.2,52.78 v1(116.59,52.4)
FXM_JTMS: length 15.7
  TOP w0.102: v1(108.09,49.87) 108.64,49.87 109,49.51 U1.P3 ; R93.1 v1(120.77,49.68)
  BOTTOM w0.127: v1(108.09,49.87) 108.28,50.06 120.39,50.06 v1(120.77,49.68)
FXM_P0_R: length 4.1
  TOP w0.102: U1.AG3 109.78,54.92 110.74,55.88 111.89,55.88 R151.2
FXM_P2_TXN: length 6.6
  TOP w0.107: U1.AG14 105.36,55.34 105.36,56.64 106.05,57.33 106.05,61.16 C271.1
FXM_P2_TXP: length 7.1
  TOP w0.107: U1.AF15 104.78,55.19 105.08,55.49 105.08,56.76 105.77,57.44 105.77,61.12 C270.1
FXM_POR_N: length 45.7
  TOP w0.102: v1(108.14,47.42) U1.K6
  TOP w0.127: v1(127.64,47.56) 126.94,46.86 v1(123.19,46.86)
  BOTTOM w0.102: R68.1 113.08,47.14 111.81,47.14 C272.1 111.28,47.47 108.19,47.47 v1(108.14,47.42)
  BOTTOM w0.127: v1(123.19,46.86) 114.23,46.86 R68.1 ; R963.2 112.79,58.04 R949.2 113.14,58.04 114.19,58.04 R975.2 114.25,57.77 114.43,57.59 124.78,57.59 127.64,54.74 v1(127.64,47.56)
FXM_RCAL: length 3.1
  TOP w0.102: v1(99.31,56.31) 99.52,56.31 100.08,55.75 100.08,54.57 U1.AE26
  BOTTOM w0.127: v1(99.31,56.31) 99.31,56.97 R199.2
FXM_XTAL1: length 8.6
  TOP w0.102: U1.T27 99.36,50.37 99.24,50.25 98.8,50.25 98.66,50.11 97.75,50.11 97.7,50.16 93.57,50.16 92.81,50.93 91.56,50.93 R198.2
FXM_XTAL2: length 7.6
  TOP w0.102: U1.T29 97.83,50.38 97.82,50.39 93.68,50.39 92.89,51.18 91.5,51.18 R197.2
GPIO13: length 5.6
  TOP w0.102: R190.1 95.93,55.56 96.21,55.56 98.38,53.39 98.91,53.39 U1.AC28
  TOP w0.127: R152.2 R190.1
GPIO16: length 5.3
  TOP w0.102: U1.AE29 98.33,54.4 97.28,55.45 97.28,56.16
  TOP w0.127: R184.1 R183.2 97.09,57.86 97.09,56.52 97.28,56.32 97.28,56.16
GPIO30: length 6.5
  BOTTOM w0.089: 111.85,88.11 U66.11
  BOTTOM w0.127: 111.85,88.11 111.67,88.11 110.81,87.25 107.36,87.25 107.08,86.97 SR175.1
GPIO31: length 11.8
  TOP w0.102: R185.2 R186.1 120.11,51.46 117.7,51.46 116.7,50.46 112.05,50.46 111.97,50.38 U1.T1
HRST_N: length 6.5
  TOP w0.102: v1(108.22,48.27) 108.53,48.57 U1.M6
  BOTTOM w0.102: R203.2 R200.2 112.24,48.23 112.07,48.06 110.87,48.06 110.52,47.7 108.79,47.7 v1(108.22,48.27)
I2C_SCL: length 240.8
  TOP w0.102: R229.2 101.17,56.9 102.3,56.9 103.06,56.14 103.06,55.6 U1.AH19 ; v1(66.87,40.32) 67.12,40.07 67.12,36.39 66.36,35.62 62.52,35.62 U601.6
  TOP w0.127: v1(24.07,144.72) 24.26,144.53 24.26,144.03 R350.1 24.32,143.3 24.32,143 23.88,142.56 U22.3 ; v1(53.85,88.27) 54.04,88.46 57.89,88.46 61.47,92.03 61.47,126.56 61.72,126.81 61.72,139.7 48.45,152.97 40.7,152.97 ; v1(66.87,48.01) 66.67,47.82 51.12,47.82 50.42,48.51 50.42,49.4 v1(50.67,49.66) ; U27.3 37.21,153.1 37.34,152.97 40.7,152.97 ; 40.7,152.97 v1(40.7,153.23) ; R229.2 100.35,57.99 100.58,58.23 100.58,61.53 98.87,63.25 91.19,63.25 88.77,60.83 88.77,58.48 v1(89.03,58.23)
  L3 w0.127: v1(66.87,40.32) 67.06,40.51 67.06,48.01 ; v1(40.7,153.23) 40.45,152.97 40.13,152.97 39.75,152.59 39.75,149.86 38.16,148.27 27.18,148.27 24.32,145.41 24.32,144.97 v1(24.07,144.72) ; v1(66.87,48.01) 67.06,48.01 ; 67.06,48.01 67.06,51.12 70.48,54.55 81.85,54.55 86.04,58.74 88.52,58.74 v1(89.03,58.23) ; v1(53.85,88.27) 53.66,88.07 53.66,78.36 50.44,75.14 50.44,49.89 v1(50.67,49.66)
I2C_SDA: length 242
  TOP w0.102: U601.5 62.85,35.19 63.03,35.37 66.48,35.37 67.37,36.26 67.37,40.13 v1(67.56,40.32) ; U1.AF19 103.16,54.87 103.16,55.31 103.28,55.43 103.28,56.23 102.43,57.09 101.66,57.09 101.35,57.4 R230.2
  TOP w0.127: v1(40.7,152.53) 40.7,152.72 ; 40.7,152.72 48.35,152.72 61.47,139.59 61.47,126.94 61.21,126.68 61.21,92.14 57.78,88.71 53.59,88.71 v1(53.15,88.27) ; 40.7,152.72 37.34,152.72 37.22,152.6 U27.2 ; v1(88.33,58.23) 88.52,58.42 88.52,60.96 91.06,63.5 99,63.5 100.84,61.66 100.84,58.11 100.95,57.99 R230.2 ; v1(49.91,49.66) 50.16,49.4 50.16,48.41 51.01,47.56 67.12,47.56 v1(67.56,48.01) ; v1(24.77,144.72) 24.57,144.53 24.57,144.03 R351.1 24.57,143.37 24.57,143 25.15,142.43 U22.2
  L3 w0.127: v1(67.56,48.01) 67.33,48.01 ; 67.33,48.01 67.33,40.56 v1(67.56,40.32) ; 67.33,48.01 67.33,51.01 70.61,54.29 81.98,54.29 86.17,58.48 88.07,58.48 v1(88.33,58.23) ; v1(40.7,152.53) 40.51,152.72 40.26,152.72 40.01,152.46 40.01,149.73 38.29,148.02 27.3,148.02 24.57,145.29 24.57,144.91 v1(24.77,144.72) ; v1(49.91,49.66) 50.19,49.93 50.19,75.27 53.4,78.49 53.4,88.01 v1(53.15,88.27)
INT_PHY_N: length 87.6
  TOP w0.127: U1.AB29 98.16,52.97 96.9,54.23 95.38,54.23 92.93,56.68 92.93,60.54 v1(93.47,61.09) ; v1(106.87,73.03) 106.87,67.37 108.78,65.47 108.78,61.4 108.9,61.28 v1(108.9,61.21) ; E1U1.56 84.48,94.29 85.02,93.76 ER331.2 85.02,87.49 84.39,86.87 v1(84.39,84.96)
  L3 w0.127: v1(108.9,61.21) 108.58,61.53 93.92,61.53 v1(93.47,61.09) ; v1(84.39,84.96) 84.39,75.37 87,72.77 106.62,72.77 v1(106.87,73.03)
LAS_N: length 4
  TOP w0.229: U601.20 57.95,35.19
  TOP w0.292: 57.95,35.19 57.12,35.19 L601.2 56.78,35.17 55.57,35.17 55.35,35.39 U602.12
LAS_P: length 4
  TOP w0.229: U601.21 57.91,34.79 57.89,34.77
  TOP w0.292: U602.11 55.42,34.59 55.57,34.75 56.78,34.75 L603.2 57.17,34.77 57.89,34.77
LED00_STR_INI_MODE1: length 7.7
  BOTTOM w0.089: 111.85,88.41 112.3,88.41 U66.12
  BOTTOM w0.127: 111.85,88.41 111.59,88.41 110.68,87.5 109.3,87.5 SC158.2 SR133.2 107.49,87.5 106.22,87.5 105.71,88.01 SR39.1
LED09_STR_REG_IF_SEL_1: length 10
  TOP w0.127: SR71.1 105.71,88.85 106.11,88.46 107.49,88.46 SR129.2 SC239.2 108.85,89.15 109.11,89.41 109.86,89.41 110.11,89.66 110.11,90.75 v1(109.92,90.94)
  BOTTOM w0.089: 112,91.11 U66.23
  BOTTOM w0.127: 112,91.11 111.52,91.11 111.38,91.25 110.23,91.25 v1(109.92,90.94)
LED15_STR_EN_PHY_R_FRC: length 6.7
  BOTTOM w0.089: U66.25 111.95,91.61
  BOTTOM w0.127: 111.95,91.61 111.78,91.61 111.63,91.76 109.17,91.76 SC246.2 SR79.2 106.74,91.23 SR96.1
LED18_STR_EN_PHY: length 7.6
  BOTTOM w0.127: U66.30 110.08,92.86 109.66,93.28 109.66,94.69 SC235.2 SR132.2 107.3,95.71 107.29,95.69 SR58.1
LED21_STR_EN_SLV_MDC_DEG: length 6.9
  BOTTOM w0.127: SR41.1 107.06,92.9 107.17,93.01 SR40.2 SC253.2 109.17,93.01 109.92,92.27 111.82,92.27 111.98,92.11 U66.27
LED24_STR_POB_EN: length 6
  BOTTOM w0.254: SR119.2 125.94,91.26 125.53,90.86 U66.88
  BOTTOM w0.508: SR127.1 128.68,91.26 SC236.2 SR119.2
LED26_STR_EN_PLED: length 6.5
  BOTTOM w0.203: SR50.2 126,93.11 125.98,93.13 125.7,93.13 124.29,91.71 123.57,91.71 123.42,91.86 U66.84
  BOTTOM w0.508: SR51.1 127.4,93.09 SC249.2 SR50.2
LED27_STR_EE_MOD: length 7.4
  BOTTOM w0.203: U66.82 123.4,92.36 123.67,92.1 124.16,92.1 125.68,93.61 125.68,94.13
  BOTTOM w0.305: 125.68,94.13 SC435.2
  BOTTOM w0.508: SR56.1 128.84,94.88 SR124.2 SC435.2
LED28_STR_SYS_LED_EN: length 8.8
  TOP w0.127: SR76.1 105.71,87.9 106.11,87.5 107.49,87.5 SC240.2 SR74.2 109.3,87.5 110.49,87.5 110.89,87.91 v1(110.89,88.39)
  BOTTOM w0.089: 111.85,88.67 111.97,88.67 112.03,88.61 U66.13
  BOTTOM w0.127: v1(110.89,88.39) 110.94,88.39 111.21,88.67 111.85,88.67
LED29: length 3.7
  BOTTOM w0.089: 111.85,87.84 112.33,87.84 U66.10
  BOTTOM w0.127: SC248.2 109.14,86.87 109.27,87 110.98,87 111.82,87.84 111.85,87.84
LED_1G_1_G: length 125
  TOP w0.127: v1(109.32,92.23) 108.71,92.84 SC275.2 108.57,92.69 108.27,92.39 107.38,92.39 106.36,93.41 v1(105.28,93.41) ; TP15.1 61.96,15.54 R838.2 CE38.1 R196.2 64.96,16.13 65.09,16.26 69.91,16.26 71.37,17.72 71.37,58.42 88.84,75.88 v1(88.84,77.15)
  L3 w0.127: v1(96.27,99.19) 95.89,99.19 95.5,98.81 94.28,98.81 92.65,97.17 92.65,80.41 89.39,77.15 v1(88.84,77.15)
  BOTTOM w0.127: U66.26 111.91,91.86 111.76,92.01 109.54,92.01 v1(109.32,92.23) ; v1(96.27,99.19) 96.9,98.55 102.93,98.55 105.09,96.39 105.09,93.6 v1(105.28,93.41)
LED_1G_1_R: length 121.6
  TOP w0.127: v1(89.28,77.66) 89.28,75.95 71.63,58.29 71.63,17.53 70.29,16.19 R195.1 CE36.1 R839.2 67.26,15.54 TP16.1
  L3 w0.127: v1(95.5,99.44) 95.12,99.06 94.18,99.06 92.39,97.28 92.39,80.52 89.53,77.66 v1(89.28,77.66)
  BOTTOM w0.127: v1(95.5,99.44) 95.76,99.69 96.39,99.69 97.28,98.81 103.06,98.81 105.35,96.52 105.35,94.04 105.73,93.66 106.24,93.66 106.73,94.16 SR49.1 106.78,94.79 SR75.2 SC247.2 109.04,94.79 109.35,94.49 109.35,93.22 110.05,92.52 112.01,92.52 112.17,92.36 U66.28
LED_2G5_2_G: length 137.6
  TOP w0.127: v1(109.28,90.61) 109.03,90.87 SC273.2 ; v1(87.69,76.2) 87.69,75.5 70.87,58.67 70.87,17.97 69.66,16.76 54.8,16.76 54.55,16.51 R189.2 CE34.1 R836.2 51.51,15.48 TP13.1
  L3 w0.127: v1(95.25,98.04) 94.32,98.04 93.15,96.88 93.15,80.2 89.15,76.2 v1(87.69,76.2)
  BOTTOM w0.127: v1(95.25,98.04) 102.68,98.04 104.58,96.14 104.58,91.36 106.16,89.79 108.84,89.79 109.28,90.23 v1(109.28,90.61) 109.41,90.49 110.11,90.49 110.62,91 111.19,91 111.32,90.87 111.32,90.86 U66.22
LED_2G5_2_R: length 131.3
  TOP w0.127: v1(106.07,90.6) 106.22,90.6 107,91.38 108.06,91.38 SC274.2 108.78,91.88 v1(109.35,91.31) ; TP14.1 56.72,15.48 R837.2 CE32.1 R180.1 59.75,15.62 60.64,16.51 69.79,16.51 71.12,17.84 71.12,58.55 88.33,75.76 v1(88.33,76.64)
  L3 w0.127: v1(96.01,98.55) 94.45,98.55 92.9,97 92.9,80.31 89.24,76.64 v1(88.33,76.64)
  BOTTOM w0.127: v1(96.01,98.55) 96.27,98.3 102.81,98.3 104.84,96.27 104.84,91.48 105.71,90.6 v1(106.07,90.6) ; U66.24 111.65,91.36 111.51,91.5 109.54,91.5 v1(109.35,91.31)
LED_2G5_3_G: length 147.5
  TOP w0.127: R835.2 CE24.1 R179.2 42.99,16.45 43.81,17.27 69.41,17.27 70.36,18.22 70.36,58.93 86.49,75.06 v1(86.49,75.31)
  L3 w0.127: v1(95.25,97.03) 94.07,97.03 93.66,96.62 93.66,79.99 88.98,75.31 v1(86.49,75.31)
  BOTTOM w0.127: U66.16 111.27,89.36 110.36,88.46 109.03,88.46 108.85,88.63 SC163.2 SR42.2 107.49,88.46 106.18,88.46 105.71,88.93 SR43.1 105.71,89.49 104.08,91.12 104.08,95.89 102.43,97.54 96.52,97.54 96.01,97.03 v1(95.25,97.03)
LED_2G5_3_R: length 142.2
  TOP w0.127: v1(87.12,75.76) 87.12,75.31 70.61,58.8 70.61,18.1 70.17,17.65 69.53,17.02 49.4,17.02 49.02,16.64 R178.1 SC267.2 CE29.1 R833.2 45.56,15.48 45.54,15.49 TP11.1
  L3 w0.127: v1(95.76,97.54) 94.2,97.54 93.41,96.75 93.41,80.1 89.07,75.76 v1(87.12,75.76)
  BOTTOM w0.127: v1(95.76,97.54) 96.14,97.54 96.39,97.79 102.55,97.79 104.33,96.01 104.33,91.24 106.03,89.53 110.11,89.53 110.3,89.73 111.82,89.73 111.96,89.86 U66.18
LED_10G_4_G: length 158.7
  TOP w0.127: v1(64.58,102.49) 65.09,101.98 69.91,101.98 71.37,100.52 71.37,98.81 71.89,98.29 E1U1.20 ; TP5.1 29.48,15.48 R831.2 CE19.1 R173.2 32.58,15.75 34.61,17.78 69.15,17.78 69.85,18.48 69.85,52.77 67.63,54.99 52.2,54.99 v1(52.01,54.8)
  L3 w0.127: v1(64.58,102.49) 64.58,101.85 61.21,98.49 61.21,92.14 54.86,85.79 54.86,77.22 51.56,73.91 51.56,55.24 v1(52.01,54.8)
LED_10G_4_R: length 152.4
  TOP w0.127: E1U1.19 71.87,98.69 71.63,98.93 71.63,101.03 TP4.1 71.18,101.09 70.04,102.23 65.53,102.23 v1(65.28,102.49) ; v1(52.07,55.5) 52.32,55.24 67.82,55.24 70.1,52.96 70.1,18.35 69.28,17.53 38.61,17.53 37.78,16.7 R175.1 CE22.1 R830.2
  L3 w0.127: v1(52.07,55.5) 51.82,55.75 51.82,73.79 55.12,77.09 55.12,85.66 61.47,92.01 61.47,98.36 65.28,102.17 v1(65.28,102.49)
LED_ETH_G: length 3.1
  TOP w0.102: U1.AD29 98.51,53.7 98.4,53.7 96.52,55.58 TP34.1
LED_ETH_R: length 7.4
  TOP w0.102: TP33.1 97.03,56.26 97.03,55.38 98.37,54.03 98.82,54.03 98.92,53.93 99.56,53.93 U1.AD27
  TOP w0.127: R193.2 R194.1 95.31,57.98 TP33.1
LED_POWER_G: length 72.9
  TOP w0.102: U1.AC26 99.34,53.39 99.14,53.19 98.28,53.19 96.29,55.18 v1(95.95,55.18)
  TOP w0.127: v1(91.34,55.59) 91.11,55.83 78.36,55.83 72.14,49.61 72.14,17.72 73.15,16.7 77.91,16.7 78.49,16.13 R832.2 CE26.1 R176.1
  L3 w0.127: v1(91.34,55.59) 95.54,55.59 v1(95.95,55.18)
LED_XPON_B: length 67.6
  TOP w0.102: v1(97.97,56.21) 98.09,56.21 98.55,55.75 98.55,55.55 99.18,54.92 U1.AG28
  TOP w0.127: R177.1 CE27.1 R834.2 73.34,16.07 71.88,17.53 71.88,49.76 78.23,56.11 91.1,56.11 v1(91.25,56.26)
  L3 w0.127: v1(97.97,56.21) 91.3,56.21 v1(91.25,56.26)
LED_XPON_R: length 2.8
  TOP w0.102: 97.61,52.37 97.88,52.11 U1.Y29
  TOP w0.127: TP9.1 96.9,53.09 97.61,52.37
MDC: length 121.4
  TOP w0.102: v1(67.06,92.84) 67.31,93.09 68.14,93.09 68.52,93.47 70.55,93.47 71.37,94.29 E1U1.30
  TOP w0.127: v1(110.05,68.64) 110.05,68.33 111.12,67.25 111.12,60.9 110.36,60.13 110.36,59.8 SR607.2 ; v1(110.43,78.23) 110.41,78.25 R235.2 SC265.1 108.15,78.25 108.14,78.23 SR69.2 ; v1(93.66,74.49) 93.66,74.23 89.79,70.36 89.79,69.47 v1(89.34,69.02)
  L3 w0.127: v1(67.06,92.84) 66.8,93.09 65.6,93.09 65.21,92.71 65.21,82.49 67.82,79.88 67.82,71.95 71.06,68.71 89.03,68.71 v1(89.34,69.02) 89.47,69.15 90.36,69.15 90.68,68.83 109.47,68.83 109.66,68.64 v1(110.05,68.64) ; v1(93.66,74.49) 93.98,74.49 97.54,78.04 110.24,78.04 v1(110.43,78.23)
  BOTTOM w0.127: v1(110.43,78.23) 110.68,77.98 111.06,77.98 113.88,80.79 113.88,82.89 115.45,84.46 U66.136
MDC_0: length 5.6
  TOP w0.102: U1.AE7 107.81,54.35 107.81,54.75 108.17,55.11 108.17,56.29 109.92,58.04 110.09,58.04 SR607.1
MDIAN0: length 34
  TOP w0.091: T17.3 93.57,113.45 93.24,113.11 93.24,111.53 93.33,111.44 93.91,111.44 D92.2 93.97,111 93.36,111 93.26,110.91 93.26,109.92 93.92,109.26 93.92,108.55 v3(94.06,108.41)
  BOTTOM w0.091: v3(94.06,108.41) 93.9,108.25 93.9,108.01 100.35,101.56 106.08,101.56 109.18,98.46 109.18,97.32 110.81,95.69 110.81,94.66 111.6,93.86 U66.34
MDIAN1: length 26.3
  TOP w0.091: v3(105.64,108.28) 105.52,108.4 105.52,110.97 105.61,111.06 106.23,111.06 D100.2 106.16,111.51 105.57,111.51 105.48,111.6 105.48,113.16 105.81,113.5 T17.15
  BOTTOM w0.091: v3(105.64,108.28) 105.49,108.14 105.49,107.61 106.14,106.96 107.65,106.96 114.2,100.41 114.2,97 115.2,96 U66.45
MDIAN2: length 23.1
  TOP w0.091: 123.83,114.56 123.83,113.66 123.36,113.2 123.36,111.66 123.45,111.57 124.01,111.57 D76.2 124.07,111.12 123.45,111.12 123.36,111.03 123.36,110.09 v3(123.5,109.96)
  BOTTOM w0.091: U66.58 118.48,95.5 118.48,96.34 118.24,96.58 118.24,97.92 118.75,98.42 118.75,100.6 123.34,105.2 123.34,109.8 v3(123.5,109.96)
MDIAP0: length 35.2
  TOP w0.091: T17.2 92.55,113.44 92.89,113.1 92.89,111.53 92.8,111.44 92.27,111.44 D92.1 92.21,111 92.83,111 92.92,110.91 92.92,109.77 93.57,109.12 93.57,108.53 v3(93.45,108.41)
  BOTTOM w0.091: U66.33 111.37,93.61 110.46,94.52 110.46,95.55 108.84,97.17 108.84,98.32 105.94,101.22 100.2,101.22 93.56,107.86 93.56,108.3 v3(93.45,108.41)
MDIAP1: length 25.5
  TOP w0.091: T17.14 104.79,113.46 105.13,113.12 105.13,111.6 105.04,111.51 104.53,111.51 D100.1 104.47,111.06 105.08,111.06 105.17,110.97 105.17,108.42 v3(105.03,108.28)
  BOTTOM w0.091: U66.44 114.85,95.56 114.85,95.86 113.86,96.86 113.86,100.27 107.51,106.62 106,106.62 105.15,107.47 105.15,108.16 v3(105.03,108.28)
MDIAP2: length 23.8
  TOP w0.091: T2.2 122.56,113.66 123.02,113.2 123.02,111.72 122.86,111.57 122.37,111.57 D76.1 122.31,111.12 122.93,111.12 123.02,111.03 123.02,110.09 v3(122.89,109.96)
  BOTTOM w0.091: v3(122.89,109.96) 122.99,109.85 122.99,105.34 118.4,100.75 118.4,98.57 117.89,98.06 117.89,96.48 118.2,96.18 U66.57
MDIBN0: length 31.9
  TOP w0.091: T17.6 96.63,113.52 96.3,113.19 96.3,109.92 96.36,109.86 96.96,109.86 D91.2 97.02,109.41 96.4,109.41 96.31,109.32 96.31,108.29 v3(96.44,108.15)
  BOTTOM w0.091: v3(96.44,108.15) 96.33,108.04 96.33,107.42 100.92,102.83 106.57,102.83 110.14,99.27 110.14,97.43 111.63,95.93 111.63,94.83 112.1,94.36 U66.36
MDIBN1: length 24.4
  TOP w0.091: T17.18 108.87,113.45 108.54,113.11 108.54,110.01 108.63,109.92 109.15,109.92 D99.2 109.21,109.47 108.6,109.47 108.5,109.38 108.5,108.59 v3(108.64,108.46)
  BOTTOM w0.091: v3(108.64,108.46) 108.48,108.3 108.48,107.97 115.22,101.24 115.22,96.92 115.7,96.44 U66.47
MDIBN2: length 24.3
  TOP w0.091: T2.6 127.64,113.66 127.17,113.2 127.17,111.66 127.26,111.57 127.88,111.57 D75.2 127.94,111.12 127.33,111.12 127.24,111.03 127.24,110.1 v3(127.36,109.98)
  BOTTOM w0.091: v3(127.36,109.98) 127.21,109.84 127.21,106.78 120.08,99.65 120.08,98.42 119.07,97.42 119.07,96.02 118.95,95.9 U66.60
MDIBP0: length 33.1
  TOP w0.091: v3(95.83,108.15) 95.97,108.29 95.97,109.32 95.87,109.41 95.26,109.41 D91.1 95.32,109.86 95.89,109.86 95.95,109.92 95.95,113.15 95.61,113.49 T17.5
  BOTTOM w0.091: U66.35 111.86,94.11 111.29,94.69 111.29,95.79 109.79,97.28 109.79,99.12 106.43,102.49 100.77,102.49 95.99,107.28 95.99,108 v3(95.83,108.15)
MDIBP1: length 23.7
  TOP w0.091: v3(108.03,108.46) 108.16,108.59 108.16,109.38 108.07,109.47 107.45,109.47 D99.1 107.51,109.92 108.1,109.92 108.19,110.01 108.19,113.11 107.85,113.44 T17.17
  BOTTOM w0.091: v3(108.03,108.46) 108.13,108.35 108.13,107.83 114.87,101.09 114.87,96.77 115.45,96.2 U66.46
MDIBP2: length 24.9
  TOP w0.091: 126.36,114.56 126.36,113.66 126.83,113.2 126.83,111.66 126.74,111.57 126.25,111.57 D75.1 126.18,111.12 126.8,111.12 126.89,111.03 126.89,110.13 v3(126.75,109.98)
  BOTTOM w0.091: U66.59 118.71,94.73 118.71,96.17 118.73,96.18 118.73,97.56 119.73,98.57 119.73,99.79 126.87,106.93 126.87,109.86 v3(126.75,109.98)
MDICN0: length 29.6
  TOP w0.091: v3(99.47,108.36) 99.36,108.46 99.36,110.91 99.45,111 100.07,111 D90.2 100,111.44 99.45,111.44 99.36,111.53 99.36,113.14 99.69,113.47 T17.9
  BOTTOM w0.091: U66.38 113.45,95.78 112.56,96.67 111.84,96.67 111.34,97.17 111.34,99.48 106.78,104.04 102.27,104.04 99.33,106.98 99.33,108.22 v3(99.47,108.36)
MDICN1: length 23.6
  TOP w0.091: T17.21 111.93,113.52 111.6,113.18 111.6,111.6 111.69,111.51 112.26,111.51 D98.2 112.32,111.06 111.71,111.06 111.62,110.97 111.62,108.88 v3(111.76,108.74)
  BOTTOM w0.091: v3(111.76,108.74) 111.59,108.57 111.59,106.7 116.17,102.12 116.17,97.87 116.65,97.39 116.65,96.2 116.7,96.15 U66.51
MDICN2: length 25.6
  TOP w0.091: v3(131.24,109.98) 131.11,110.11 131.11,111.03 131.2,111.12 131.82,111.12 D74.2 131.75,111.57 131.07,111.57 130.98,111.66 130.98,113.2 131.44,113.66 131.44,114.56
  BOTTOM w0.091: v3(131.24,109.98) 131.08,109.82 131.08,108.05 121.63,98.6 121.63,97.94 119.95,96.26 U66.64
MDICP0: length 29.5
  TOP w0.091: T17.8 98.67,113.48 99.01,113.14 99.01,111.53 98.92,111.44 98.37,111.44 D90.1 98.31,111 98.92,111 99.01,110.91 99.01,108.51 v3(98.86,108.36)
  BOTTOM w0.091: v3(98.86,108.36) 98.99,108.22 98.99,106.83 102.13,103.7 106.64,103.7 111,99.33 111,97.03 111.7,96.33 112.41,96.33 112.95,95.8 U66.37
MDICP1: length 22.8
  TOP w0.091: T17.20 110.91,113.5 111.25,113.16 111.25,111.6 111.16,111.51 110.63,111.51 D98.1 110.56,111.06 111.18,111.06 111.27,110.97 111.27,108.86 v3(111.15,108.74)
  BOTTOM w0.091: U66.50 116.4,95.51 116.4,95.97 116.3,96.06 116.3,97.25 115.82,97.73 115.82,101.98 111.24,106.56 111.24,108.64 v3(111.15,108.74)
MDICP2: length 26
  TOP w0.091: T2.8 130.18,113.66 130.64,113.2 130.64,111.66 130.55,111.57 130.12,111.57 D74.1 130.06,111.12 130.67,111.12 130.76,111.03 130.76,110.11 v3(130.63,109.98)
  BOTTOM w0.089: 119.7,95.93 U66.63
  BOTTOM w0.091: 119.7,95.93 119.7,96.5 121.28,98.09 121.28,98.74 130.74,108.2 130.74,109.88 v3(130.63,109.98)
MDIDN0: length 28
  TOP w0.091: v3(102.54,108.23) 102.41,108.36 102.41,109.38 102.5,109.47 103.11,109.47 D89.2 103.05,109.92 102.51,109.92 102.42,110.01 102.42,113.15 102.75,113.49 T17.12
  BOTTOM w0.091: U66.42 114.45,95.8 112.99,97.25 112.99,99.6 107.7,104.9 103.74,104.9 102.38,106.26 102.38,108.07 v3(102.54,108.23)
MDIDN1: length 24.5
  TOP w0.091: T17.24 114.99,113.47 114.66,113.13 114.66,109.95 114.75,109.86 115.24,109.86 D97.2 115.31,109.41 114.69,109.41 114.6,109.32 114.6,108.56 v3(114.73,108.43)
  BOTTOM w0.091: U66.53 117.2,96.24 117.35,96.39 117.35,103.46 118.26,104.38 118.26,106.32 117.17,107.41 115.01,107.41 114.65,107.78 114.65,108.35 v3(114.73,108.43)
MDIDN2: length 27.7
  TOP w0.091: T2.12 135.25,113.66 134.79,113.2 134.79,111.66 134.88,111.57 135.63,111.57 D73.2 135.69,111.12 135.07,111.12 134.98,111.03 134.98,110.1 v3(135.1,109.98)
  BOTTOM w0.091: v3(135.1,109.98) 134.96,109.84 134.96,109.11 122.97,97.13 121.81,97.13 120.46,95.78 120.46,95.47 U66.66
MDIDP0: length 27.9
  TOP w0.091: T17.11 101.73,113.47 102.07,113.13 102.07,110.01 101.98,109.92 101.42,109.92 D89.1 101.36,109.47 101.97,109.47 102.06,109.38 102.06,108.36 v3(101.93,108.23)
  BOTTOM w0.091: U66.40 113.95,95.81 112.65,97.11 112.65,99.46 107.55,104.56 103.6,104.56 102.04,106.12 102.04,108.12 v3(101.93,108.23)
MDIDP1: length 23.9
  TOP w0.091: 114.25,108.56 v3(114.12,108.43) ; 114.25,108.56 114.25,108.56 ; 114.25,108.56 114.25,109.32 114.16,109.41 113.55,109.41 D97.1 113.61,109.86 114.22,109.86 114.31,109.95 114.31,113.15 113.97,113.48 T17.23
  BOTTOM w0.091: U66.52 116.95,96.5 117,96.56 117,103.6 117.92,104.52 117.92,106.17 117.03,107.06 114.87,107.06 114.3,107.63 114.3,108.25 v3(114.12,108.43)
